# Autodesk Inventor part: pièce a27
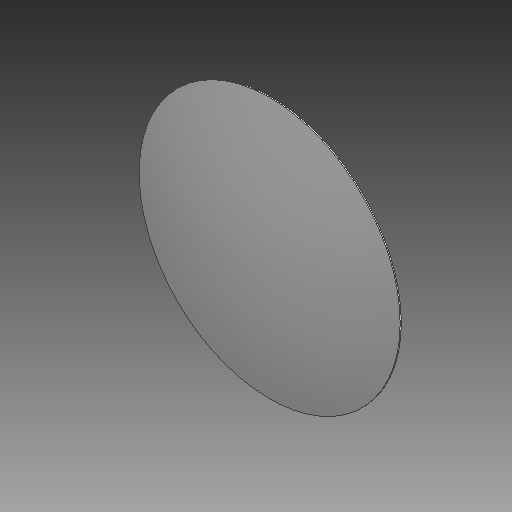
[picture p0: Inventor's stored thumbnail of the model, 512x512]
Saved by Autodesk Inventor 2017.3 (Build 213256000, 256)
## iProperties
Created: 2008-01
Part Number: pièce a27
Material: Générique
Document SubType Name: Modeling
Designer: ficho
Density: 1 g/cm^3
Appearance: Par défaut
Author: ficho
Sending System: SolidWorks 2009
Last Author: christophe
Last Saved: 2011-02-10
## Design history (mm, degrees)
feature "Dôme2"
node "Solide1"
